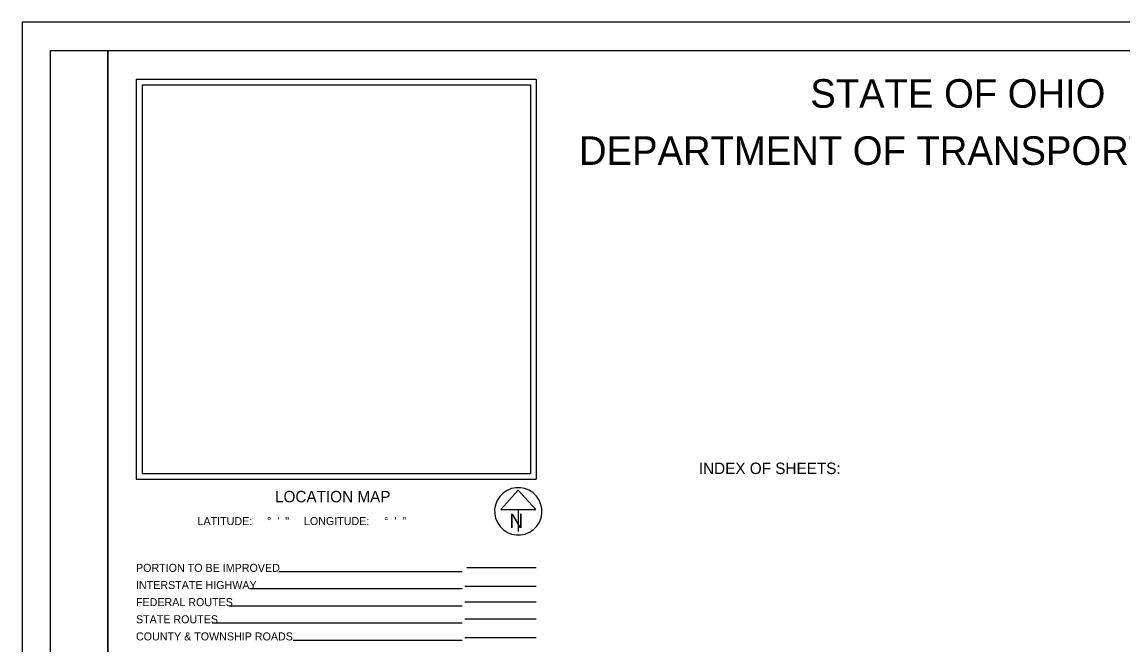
# Model space of a CAD drawing. Extents: x -15 to 405, y -40 to 87.
# Drawn here: x 52.16 to 71.42, y -29.19 to -18.29 of the extents above; entities that cross this region are included whole.
import ezdxf

# ---------------------------------------------------------------- set-up
doc = ezdxf.new("R2010")
doc.units = 0
for name, color, linetype in [('GM_X_Adjacent_County', 7, 'Continuous'), ('GM_X_County', 7, 'Continuous'), ('GM_X_Section', 7, 'Continuous'), ('GM_X_Township', 7, 'Continuous')]:
    doc.layers.add(name, color=color, linetype=linetype)

msp = doc.modelspace()

# ---------------------------------------------------------------- linework, layer by layer
at = {"layer": 'GM_X_County'}
for points in [[(52.656, -18.787), (53.656, -18.787), (53.656, -39.787), (52.656, -39.787)], [(53.656, -18.787), (85.656, -18.787), (85.656, -39.787), (53.656, -39.787)]]:
    msp.add_lwpolyline(points, close=True, dxfattribs=at)
at = {"layer": 'GM_X_Section'}
msp.add_lwpolyline([(52.156, -40.287), (86.156, -40.287), (86.156, -18.287), (52.156, -18.287)], close=True, dxfattribs=at)
at = {"layer": 'GM_X_Township'}
for p, q in [((54.156, -19.287), (61.156, -19.287)), ((54.156, -19.287), (54.156, -26.287)), ((54.256, -19.387), (54.256, -26.187)), ((54.256, -19.387), (61.056, -19.387)), ((61.056, -19.387), (61.056, -26.187)), ((61.156, -19.287), (61.156, -26.287)), ((54.256, -26.187), (61.056, -26.187)), ((54.256, -26.187), (54.256, -26.187)), ((54.156, -26.287), (61.156, -26.287)), ((60.84, -26.478), (60.533, -26.819)), ((61.148, -26.819), (60.84, -26.478)), ((60.533, -26.819), (61.148, -26.819)), ((60.84, -26.819), (60.84, -27.206)), ((60.84, -26.851), (60.84, -26.851)), ((60.84, -26.851), (60.84, -26.851)), ((59.856, -27.91), (56.649, -27.91)), ((59.938, -27.831), (61.156, -27.831)), ((59.856, -28.21), (56.145, -28.21)), ((61.156, -28.166), (59.906, -28.166)), ((59.856, -28.51), (55.775, -28.51)), ((61.156, -28.438), (59.906, -28.438)), ((59.856, -28.81), (55.485, -28.81)), ((61.156, -28.738), (59.906, -28.738)), ((61.156, -29.064), (59.906, -29.064)), ((59.856, -29.11), (56.901, -29.11))]:
    msp.add_line(p, q, dxfattribs=at)
msp.add_arc((60.84, -26.851), 0.415, 129.7798, 129.7633, dxfattribs=at)

# ---------------------------------------------------------------- texts
at = {"layer": 'GM_X_Adjacent_County'}
for s, height, p in [('STATE OF OHIO', 0.5, (65.951, -19.787)), ('DEPARTMENT OF TRANSPORTATION', 0.5, (61.902, -20.787)), ('INDEX OF SHEETS:', 0.2, (64, -26.198)), ('LOCATION MAP', 0.2, (56.583, -26.693)), ('LATITUDE:     °  \'  "     LONGITUDE:     °  \'  "', 0.14, (55.227, -27.091)), ('PORTION TO BE IMPROVED', 0.14, (54.15, -27.91)), ('INTERSTATE HIGHWAY', 0.14, (54.15, -28.21)), ('FEDERAL ROUTES', 0.14, (54.15, -28.51)), ('STATE ROUTES', 0.14, (54.15, -28.81)), ('COUNTY & TOWNSHIP ROADS', 0.14, (54.15, -29.11))]:
    msp.add_text(s, height=height, dxfattribs=at).set_placement(p)
at = {"layer": 'GM_X_Township'}
msp.add_text('N', height=0.25, dxfattribs=at).set_placement((60.685, -27.143))

doc.saveas('drawing.dxf')
